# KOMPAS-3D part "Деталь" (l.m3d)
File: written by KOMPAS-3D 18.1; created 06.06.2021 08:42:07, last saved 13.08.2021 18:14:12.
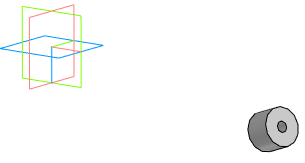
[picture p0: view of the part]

Document properties: Автор: 111; Полное имя файла: C:\Users\admin\Desktop\ffb\l.m3d

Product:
- Part/product: Деталь
    Масса: 0.0888493

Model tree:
1. Эскиз:1
2. Элемент выдавливания:1
     Расстояние 1 = 20
3. Элемент выдавливания:2
     Расстояние 1 = 10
